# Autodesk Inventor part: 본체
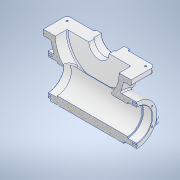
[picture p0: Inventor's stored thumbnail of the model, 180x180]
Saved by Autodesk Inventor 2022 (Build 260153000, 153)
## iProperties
Created: 2023-07
Part Number: 본체
Material: 알루미늄 6061
Document SubType Name: Modeling
Designer: PC-01
Density: 2.7 g/cm^3
Appearance: 알루미늄 - 평지
Author: PC-01
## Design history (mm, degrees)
sketch "스케치1"
  geometry: C1 r 55 at (0, 0); 1 further point
  constraints: 1 centre point, 1 coincident
  dimensions: "d0" = 110 diameter of C1
extrude "돌출1" new body sketch "스케치1" stored distance "d1" = 242; taper "d2" = 0 deg
sketch "스케치2"
  geometry: C1 r 42.5 at (0, 0); 1 further point
  constraints: 1 centre point, 1 coincident
  dimensions: "d3" = 85 diameter of C1
extrude "돌출2" cut sketch "스케치2" distance "d4" = 25; taper "d5" = 0 deg
sketch "스케치3" dims "d6" = 97
  geometry: L1 (0, 0)-(0, 48.5); 1 further point
  constraints: 2 end point, 1 coincident, 1 vertical, 1 vertical alignment, 2 other
hole "구멍1" sketch "스케치3" at (0, 48.5) diameter "d7" = 4.134; stored, may be unused: countersink angle "d11" = 90 deg, drill point angle "d13" = 118 deg; dims "d8" = 10, "d9" = 4, "d10" = 2, "d12" = 12
sketch "스케치4"
  geometry: C1 r 38.5 at (0, 0); 1 further point
  constraints: 1 centre point, 1 coincident
  dimensions: "d17" = 77 diameter of C1
extrude "돌출3" cut sketch "스케치4" extent not by distance; stored distance "d18" = 0; taper "d19" = 0 deg
node "작업 평면1"
sketch "스케치5"
  geometry: L1 (114, -100)-(-86, -100); L2 (-86, -100)-(-86, 100); L3 (-86, 100)-(114, 100); L4 (114, 100)-(114, -100); L5 (121, -55)-(121, 55) reference; 2 further points
  constraints: 8 end point, 2 parallel, 1 horizontal, 1 horizontal alignment, 1 midpoint, 1 perpendicular
  dimensions: "d21" = 200 distance of L1.end L2.end; "d22" = 200 distance of L1.start L1.end; "d23" = 7 distance between parallel lines of L4 L5
extrude "돌출4" join sketch "스케치5" distance "d24" = 15; taper "d25" = 0 deg
sketch "스케치7" dims "d35" = 200
  geometry: L1 (-14, 100)-(-14, -60); L2 (86, -60)-(-114, -60) reference; L3 (-14, 100)-(-134, 100); L4 (-134, 100)-(-134, 85); L5 (-134, 85)-(-112.869, 85); L6 (-14, 100)-(106, 100); L7 (106, 100)-(106, 85); L8 (106, 85)-(84.869, 85); 2 further points
  constraints: 14 end point, 3 symmetric about line, 2 perpendicular, 1 coincident, 1 horizontal, 1 midpoint, 1 vertical, 3 other
  dimensions: "d34" = 160 distance of L1.start L1.end; "d36" = 120 distance of L3.start L3.end; "d37" = 15 distance of L3.end L4.end
extrude "돌출6" join sketch "스케치7" stored distance "d38" = 130; taper "d39" = 0 deg
sketch "스케치8"
  geometry: L1 (-134, 100)-(106, 100) reference; L2 (31, 100)-(-59, 100); A1 r 45 centre (-14, 100) between (-59, 100) and (31, 100); 1 further point
  constraints: 2 end point, 2 point on circle, 2 point on line, 1 centre point, 1 horizontal, 1 midpoint
  dimensions: "d40" = 90 diameter of A1
extrude "돌출7" join sketch "스케치8" distance "d41" = 5; taper "d42" = 0 deg
sketch "스케치9"
  geometry: L1 (31, 100)-(-59, 100) reference; C1 r 31 at (-14, 100); A1 r 45 centre (-14, 100) between (-59, 100) and (31, 100) reference; 1 further point
  constraints: 1 centre point, 1 coincident
  dimensions: "d43" = 62 diameter of C1
extrude "돌출8" cut sketch "스케치9" distance "d44" = 23; taper "d45" = 0 deg
sketch "스케치10"
  geometry: L1 (-45, 100)-(17, 100) reference; C1 r 27.5 at (-14, 100); A1 r 31 centre (-14, 100) between (-45, 100) and (17, 100) reference; 1 further point
  constraints: 1 centre point, 1 coincident
  dimensions: "d46" = 55 diameter of C1
extrude "돌출9" cut sketch "스케치10" extent not by distance; stored distance "d47" = 23; taper "d48" = 0 deg
sketch "스케치11"
  geometry: L1 (31, 100)-(17, 100) reference; L2 (-45, 100)-(-59, 100) reference; C1 r 87 at (-14, 100); A1 r 31 centre (-14, 100) between (-45, 100) and (17, 100) reference; A2 r 45 centre (-14, 100) between (-59, 100) and (31, 100) reference; 1 further point
  constraints: 1 centre point, 1 coincident
  dimensions: "d49" = 174 diameter of C1
  node "투영된 루프3"
extrude "돌출10" cut sketch "스케치11" stored distance "d50" = 64; taper "d51" = 0 deg
extrude "돌출11" cut sketch "스케치4" extent not by distance; stored distance "d52" = 0; taper "d53" = 0 deg
fillet "모깎기1" dims "d54" = 10
fillet "모깎기2" dims "d55" = 10
sketch "스케치12"
  geometry: L1 (-114, 90)-(-114, 31.623) reference; L2 (86, 31.623)-(-114, 31.623) reference; L3 (86, 31.623)-(86, 90) reference; L4 (76, 100)-(-104, 100) reference; L5 (86, -90)-(86, -31.623) reference; L6 (-114, -31.623)-(86, -31.623) reference; L7 (-114, -31.623)-(-114, -90) reference; L8 (-104, -100)-(76, -100) reference; L9 (76, 100)-(-104, 100) reference; L10 (-104, -100)-(76, -100) reference; L11 (-14, -100)-(-14, -119.667); C1 r 14 at (-94, 80); C2 r 14 at (66, 80); C3 r 14 at (-94, -80); C4 r 14 at (66, -80); A1 r 10 centre (-104, 90) between (-104, 100) and (-114, 90) reference; A2 r 10 centre (76, 90) between (86, 90) and (76, 100) reference; A3 r 10 centre (76, -90) between (76, -100) and (86, -90) reference; A4 r 10 centre (-104, -90) between (-114, -90) and (-104, -100) reference; 1 further point
  constraints: 4 centre point, 2 end point, 2 horizontal alignment, 2 vertical alignment, 1 midpoint, 1 vertical
  dimensions: "d56" = 28 diameter of C1; "d57" = 28 diameter of C2; "d58" = 28 diameter of C3; "d59" = 28 diameter of C4; "d60" = 160 distance of C3.centre C1.centre; "d61" = 160 distance of C2.centre C1.centre; "d62" = 80 vertical distance of point (0, 0) C1.centre; "d63" = 80 horizontal distance of L11.start C1.centre
extrude "돌출12" cut sketch "스케치12" distance "d64" = 2; taper "d65" = 0 deg
sketch "스케치13"
  geometry: C1 r 14 at (0, 0) reference; 2 further points
  constraints: 1 coincident
hole "구멍2" sketch "스케치13" at (0, 0) diameter "d66" = 11; stored, may be unused: countersink angle "d70" = 90 deg, drill point angle "d72" = 118 deg; dims "d67" = 10, "d68" = 4, "d69" = 2, "d71" = 12
sketch "스케치14"
  geometry: C1 r 14 at (0, 0) reference; 2 further points
  constraints: 1 coincident
hole "구멍3" sketch "스케치14" at (0, 0) diameter "d73" = 11; stored, may be unused: countersink angle "d77" = 90 deg, drill point angle "d79" = 118 deg; dims "d74" = 6, "d75" = 4, "d76" = 2, "d78" = 12
sketch "스케치15"
  geometry: C1 r 14 at (0, 0) reference; 2 further points
  constraints: 1 coincident
hole "구멍4" sketch "스케치15" at (0, 0) diameter "d80" = 11; stored, may be unused: countersink angle "d84" = 90 deg, drill point angle "d86" = 118 deg; dims "d81" = 6, "d82" = 4, "d83" = 2, "d85" = 12
sketch "스케치16"
  geometry: C1 r 14 at (0, 0) reference; 2 further points
  constraints: 1 coincident
hole "구멍5" sketch "스케치16" at (0, 0) diameter "d87" = 11; stored, may be unused: countersink angle "d91" = 90 deg, drill point angle "d93" = 118 deg; dims "d88" = 6, "d89" = 4, "d90" = 2, "d92" = 12
sketch "스케치17"
  geometry: L1 (-62, 114.069)-(-50, 114.069) reference; L2 (-75, 125)-(-75, 15) reference; L3 (0, 5)-(-65, 5) reference; L4 (0, 5)-(0, 0) reference; L5 (14, 0)-(0, 0) reference; L6 (14, 0)-(14, 23) reference; L7 (14, 23)-(17.5, 23) reference; L8 (17.5, 23)-(17.5, 38) reference; L9 (17.5, 38)-(-42, 38) reference; L10 (-42, 38)-(-42, 102) reference; L11 (-42, 102)-(17.5, 102) reference; L12 (17.5, 102)-(17.5, 117) reference; L13 (17.5, 117)-(14, 117) reference; L14 (14, 117)-(14, 140) reference; L15 (14, 140)-(0, 140) reference; L16 (0, 135)-(0, 140) reference; L17 (-65, 135)-(0, 135) reference; L18 (135, 170)-(-45, 170) reference; L19 (45, 170)-(45, 190.033); A1 r 10 centre (-65, 125) between (-65, 135) and (-75, 125) reference; A2 r 10 centre (-65, 15) between (-75, 15) and (-65, 5) reference; 5 further points
  constraints: 2 end point, 2 symmetric about line, 1 midpoint, 1 vertical, 1 vertical alignment
  dimensions: "d94" = 104 distance of point (-62, 18) point (-62, 122); "d95" = 52 vertical distance of point (59, 70) point (-62, 122); "d96" = 107 horizontal distance of L19.end point (-62, 122)
hole "구멍6" sketch "스케치17" at (-62, 122), (-62, 18), (152, 18), (152, 122) diameter "d97" = 4.917; stored, may be unused: countersink angle "d101" = 90 deg, drill point angle "d103" = 118 deg; dims "d98" = 10, "d99" = 4, "d100" = 2, "d102" = 12
sketch "스케치18"
  geometry: L1 (-45, 100)-(-59, 100) reference; L2 (31, 100)-(17, 100) reference; L3 (-14, 100)-(-14, 69); L4 (-14, 100)-(12.163, 73.837); L5 (-14, 100)-(-40.163, 73.837); A1 r 31 centre (-14, 100) between (-45, 100) and (17, 100) reference; A2 r 45 centre (-14, 100) between (-59, 100) and (31, 100) reference; A3 r 37 centre (-14, 100) between (12.163, 73.837) and (-40.163, 73.837); 1 further point
  constraints: 6 end point, 3 point on circle, 1 centre point, 1 coincident
  dimensions: "d104" = 74 diameter of A3; "d105" = 45 deg angle of L3 L4; "d106" = 45 deg angle of L3 L5
hole "구멍7" sketch "스케치18" at (-40.163, 73.837), (12.163, 73.837) diameter "d107" = 4.134; stored, may be unused: countersink angle "d111" = 90 deg, drill point angle "d113" = 118 deg; dims "d108" = 10, "d109" = 4, "d110" = 2, "d112" = 12
fillet "모깎기3" dims "d114" = 15
fillet "모깎기4" dims "d115" = 3
fillet "모깎기5" dims "d116" = 3
fillet "모깎기6" dims "d117" = 3
fillet "모깎기8" dims "d119" = 1
chamfer "모따기1" distance "d120" = 1; stored, may be unused: second distance "d121" = 2, angle "d122" = 45 deg
sketch "스케치19"
  geometry: L1 (-46, 100)-(-59, 100) reference; L2 (31, 100)-(18, 100) reference; L3 (-14, 100)-(-14, 85); L4 (96, 85)-(84.869, 85) reference; L5 (-14, 85)-(84.869, 85); L6 (-14, 85)-(-112.869, 85); C1 r 2.067 at (12.163, 73.837) reference; C2 r 2.067 at (-40.163, 73.837) reference; A1 r 32 centre (-14, 100) between (-46, 100) and (18, 100) reference; A2 r 45 centre (-14, 100) between (-59, 100) and (31, 100) reference; A3 r 100 centre (-14, 100) between (-114, 100) and (86, 100); 3 further points
  constraints: 6 end point, 3 point on circle, 2 point on line, 1 centre point, 1 coincident, 1 horizontal, 1 vertical
  dimensions: "d126" = 200 diameter of A3; "d127" = 15 distance of L3.start L3.end
extrude "돌출13" cut sketch "스케치19" distance "d128" = 20; taper "d129" = 0 deg
sketch "스케치20"
  geometry: L1 (0, 0)-(0, -55); L2 (0, 0)-(0, 55); L3 (0, 55)-(0, 45) reference; C1 r 55 at (0, 0); C2 r 38.5 at (0, 0) reference; C3 r 42.5 at (0, 0) reference; A1 r 55 centre (0, 0) between (0, -55) and (0, 55) reference; 5 further points
  constraints: 4 end point, 2 point on circle, 1 centre point, 1 coincident, 1 point on line, 1 vertical
  dimensions: "d130" = 110 diameter of C1
extrude "돌출14" join sketch "스케치20" stored distance "d131" = 210; taper "d132" = 0 deg
extrude "돌출15" cut sketch "스케치11" stored distance "d133" = 64; taper "d134" = 0 deg
fillet "모깎기12" dims "d135" = 3
fillet "모깎기13" dims "d136" = 3
fillet "모깎기14" dims "d137" = 3
fillet "모깎기15" dims "d138" = 3
fillet "모깎기16" dims "d139" = 3
fillet "모깎기17" dims "d140" = 3
fillet "모깎기18" dims "d141" = 3
sketch "스케치21"
  geometry: L1 (-104, -100)-(76, -100) reference; L2 (13.5, -47)-(-41.5, -47) reference; 3 further points
  constraints: 1 midpoint, 1 vertical alignment, 1 other
  dimensions: "d142" = 15 distance from line of L1 point (-14, -85)
feature "엠보싱1" sketch "스케치21" dims "d14" = 60, "d143" = 0.5, "d144" = 0
fillet "모깎기19" dims "d145" = 1
node "솔리드1"
pattern_circular "원형 패턴1" dims angle "d15" = 360 deg
mirror "미러1"
mirror "미러2"
mirror "미러3"
mirror "미러4"
mirror "미러5"
node "투영된 루프1"
node "투영된 루프2"
node "투영된 루프4"
node "투영된 루프5"
node "투영된 루프6"
node "투영된 루프7"
node "투영된 루프8"
node "투영된 루프9"
feature "A9D066F2-1C7D-4E18-AEED-F7BC21143FA4" dims "d66" = 11, "d67" = 10, "d68" = 4, "d69" = 2, "d70" = 90 deg, "d71" = 12, "d72" = 118 deg
